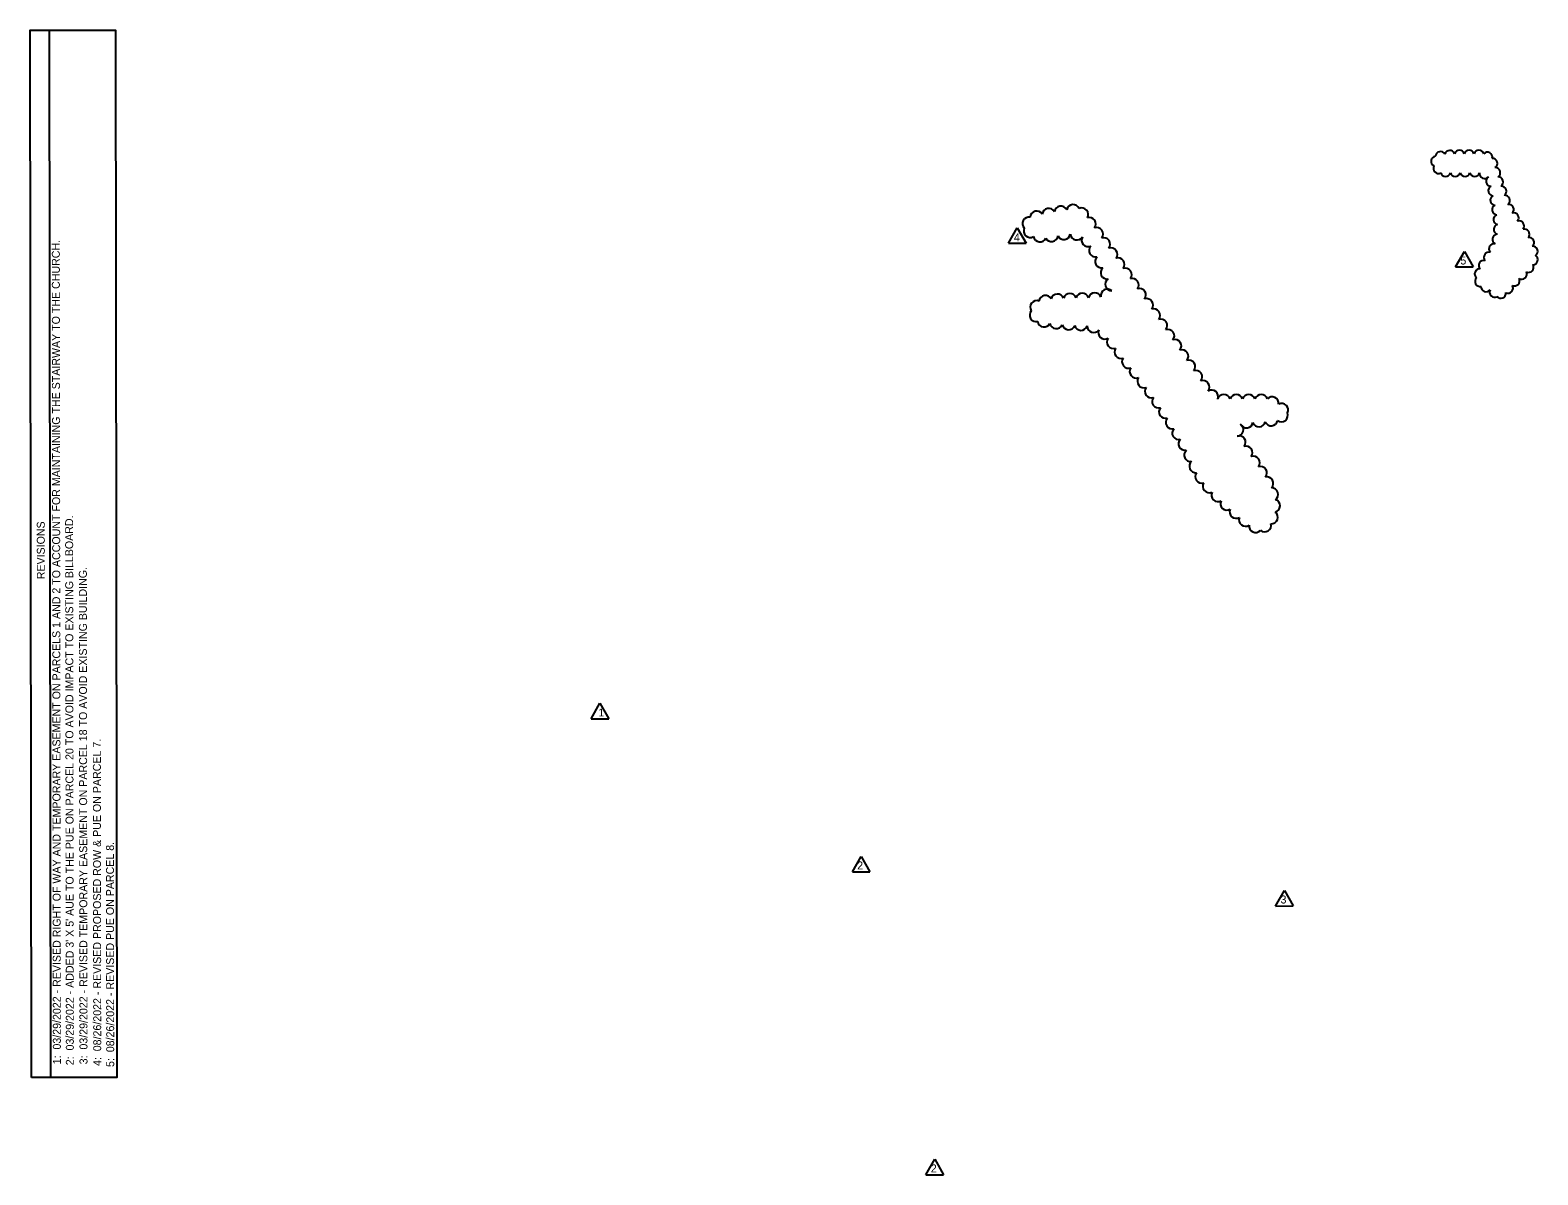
# Model space of a CAD drawing. Extents: x 1882804 to 2194450, y 87424 to 845437.
# Drawn here: x 1882804 to 1883942, y 844572 to 845437 of the extents above; entities that cross this region are included whole.
import ezdxf

# ---------------------------------------------------------------- set-up
doc = ezdxf.new("R2010")
doc.units = 0
doc.layers.add('Sheet Block Revision CELL', color=7, linetype='Continuous')

msp = doc.modelspace()

# ---------------------------------------------------------------- linework, layer by layer
at = {"layer": 'Sheet Block Revision CELL'}
for p, q in [((1882819.7, 844645.9), (1882818.7, 845436.6)), ((1883542.8, 845275.7), (1883549.4, 845287.4)), ((1883549.4, 845287.4), (1883556.1, 845275.7)), ((1883542.8, 845275.7), (1883556.1, 845275.7)), ((1883880.4, 845257.9), (1883887, 845269.6)), ((1883887, 845269.6), (1883893.7, 845257.9)), ((1883880.4, 845257.9), (1883893.7, 845257.9)), ((1883227.8, 844916.7), (1883234.3, 844928.5)), ((1883234.3, 844928.5), (1883241, 844916.8)), ((1883227.8, 844916.7), (1883241, 844916.8)), ((1883425, 844801.2), (1883431.5, 844812.9)), ((1883431.5, 844812.9), (1883438.2, 844801.2)), ((1883425, 844801.2), (1883438.2, 844801.2)), ((1883744.5, 844775.4), (1883751.1, 844787.2)), ((1883751.1, 844787.2), (1883757.8, 844775.5)), ((1883744.5, 844775.4), (1883757.8, 844775.5)), ((1883480.5, 844572.5), (1883487.1, 844584.2)), ((1883487.1, 844584.2), (1883493.7, 844572.5)), ((1883480.5, 844572.5), (1883493.7, 844572.5))]:
    msp.add_line(p, q, dxfattribs=at)
msp.add_lwpolyline([(1882805.2, 844645.9), (1882804.1, 845436.5), (1882868.6, 845436.6), (1882869.6, 844646)], close=True, dxfattribs=at)
for centre, radius, start, end in [((1883865.7, 845337.6), 3.85, 98.5677, 243.5677), ((1883869, 845341.1), 3.85, 30.5512, 175.5512), ((1883876, 845342), 3.85, 19.754, 164.754), ((1883883.3, 845342.2), 3.85, 17.5071, 162.5071), ((1883890.6, 845342.2), 3.85, 17.5, 162.5), ((1883898, 845342.2), 3.85, 17.5, 162.5), ((1883904.3, 845340.6), 3.85, 349.3585, 134.3585), ((1883867.4, 845332.3), 3.85, 152.0987, 297.0987), ((1883908.1, 845336), 3.85, 305.035, 90.035), ((1883910.3, 845329), 3.85, 305.035, 90.035), ((1883872.8, 845330.1), 3.85, 197.3072, 342.3072), ((1883880.1, 845330), 3.85, 197.5, 342.5), ((1883887.5, 845330), 3.85, 197.5, 342.5), ((1883894.8, 845330), 3.85, 197.5, 342.5), ((1883902.3, 845328.5), 3.85, 173.5372, 318.5372), ((1883907.2, 845322.6), 3.85, 121.3221, 266.3221), ((1883908.9, 845315.4), 3.85, 119.8498, 264.8498), ((1883912.5, 845322), 3.85, 305.3012, 90.3012), ((1883914.9, 845315), 3.85, 306.8133, 91.8133), ((1883910.4, 845308.3), 3.85, 119.3697, 264.3697), ((1883917.5, 845308.1), 3.85, 309.2572, 94.2572), ((1883558.3, 845290.5), 4.92, 78.9337, 223.9337), ((1883564.1, 845295.1), 4.92, 32.4745, 177.4745), ((1883573.2, 845297.2), 4.92, 28.9006, 173.9006), ((1883582.3, 845298.8), 4.92, 25.4829, 170.4829), ((1883591.6, 845300), 4.92, 23.7892, 168.7892), ((1883598.1, 845297.5), 4.92, 329.7462, 114.7462), ((1883603.9, 845290.3), 4.92, 322.6712, 107.6712), ((1883911.8, 845301), 3.85, 117.6133, 262.6133), ((1883912.8, 845293.6), 3.85, 112.7454, 257.7454), ((1883920.5, 845301.3), 3.85, 313.6939, 98.6939), ((1883924.2, 845294.9), 3.85, 321.2908, 106.2908), ((1883559.2, 845285), 4.92, 155.173, 300.173), ((1883609.3, 845282.7), 4.92, 322.6712, 107.6712), ((1883913, 845286.2), 3.85, 105.6199, 250.6199), ((1883928.3, 845288.8), 3.85, 321.0615, 106.0615), ((1883932.3, 845282.6), 3.85, 319.3192, 104.3192), ((1883566.5, 845281.7), 4.92, 190.6405, 335.6405), ((1883575.3, 845281.9), 4.92, 207.3475, 352.3475), ((1883584.6, 845283.4), 4.92, 206.1246, 351.1246), ((1883594.4, 845283.1), 4.92, 184.7569, 329.7569), ((1883602.9, 845278.1), 4.92, 149.6769, 294.6769), ((1883608.5, 845270.3), 4.92, 137.3078, 282.3078), ((1883614.7, 845275), 4.92, 322.6712, 107.6712), ((1883909.4, 845271.6), 3.85, 78.7837, 223.7837), ((1883912.1, 845278.7), 3.85, 94.608, 239.608), ((1883935.8, 845276.3), 3.85, 314.1507, 99.1507), ((1883938.5, 845269.7), 3.85, 304.9848, 89.9848), ((1883613.1, 845262.1), 4.92, 135.2656, 280.2656), ((1883620.1, 845267.3), 4.92, 322.6712, 107.6712), ((1883625.5, 845259.7), 4.92, 322.6712, 107.6712), ((1883901.7, 845259), 3.85, 76.612, 221.612), ((1883905.6, 845265.2), 3.85, 74.9742, 219.9742), ((1883938.6, 845263.3), 3.85, 273.0145, 58.0145), ((1883617.3, 845253.6), 4.92, 132.867, 277.867), ((1883630.9, 845252), 4.92, 322.6599, 107.6599), ((1883898.6, 845252.6), 3.85, 85.5429, 230.5429), ((1883898.9, 845247), 3.85, 135.584, 280.584), ((1883930.3, 845252.5), 3.85, 239.3787, 24.3787), ((1883935.5, 845257.6), 3.85, 244.1441, 29.1441), ((1883608, 845233.4), 4.92, 21.0229, 166.0229), ((1883617.4, 845236.2), 4.92, 47.0123, 192.0123), ((1883620.8, 845244.7), 4.92, 124.3827, 269.3827), ((1883636.3, 845244.3), 4.92, 322.602, 107.602), ((1883641.7, 845236.6), 4.92, 322.5309, 107.5309), ((1883903.4, 845243), 3.85, 176.7583, 321.7583), ((1883909.9, 845238.8), 3.85, 152.7321, 297.7321), ((1883914.5, 845238), 3.85, 221.6581, 6.6581), ((1883919.9, 845241.9), 3.85, 246.2799, 31.2799), ((1883924.9, 845247.4), 3.85, 243.1795, 28.1795), ((1883564.1, 845227.5), 4.92, 69.0266, 214.0266), ((1883570.7, 845231.4), 4.92, 27.349, 172.349), ((1883579.8, 845232.5), 4.92, 21.2186, 166.2186), ((1883589.2, 845232.9), 4.92, 18.9869, 163.9869), ((1883598.5, 845233.1), 4.92, 17.8673, 162.8673), ((1883647.1, 845229), 4.92, 322.4483, 107.4483), ((1883563.7, 845221.5), 4.92, 138.7154, 283.7154), ((1883569.7, 845217.4), 4.92, 188.7185, 333.7185), ((1883652.4, 845221.3), 4.92, 322.3506, 107.3506), ((1883657.8, 845213.6), 4.92, 322.2326, 107.2326), ((1883578.9, 845216.2), 4.92, 191.1828, 336.1828), ((1883588.2, 845215.4), 4.92, 193.5197, 338.5197), ((1883597.5, 845214.9), 4.92, 195.9911, 340.9911), ((1883607.1, 845213.2), 4.92, 178.7047, 323.7047), ((1883615.5, 845208.3), 4.92, 155.5881, 300.5881), ((1883663.1, 845205.8), 4.92, 322.0861, 107.0861), ((1883622, 845201.2), 4.92, 144.3767, 289.3767), ((1883627.7, 845193.7), 4.92, 144.6907, 289.6907), ((1883668.4, 845198.1), 4.92, 321.8974, 106.8974), ((1883673.7, 845190.4), 4.92, 321.6411, 106.6411), ((1883633.4, 845186.3), 4.92, 145.4515, 290.4515), ((1883639.2, 845178.9), 4.92, 146.0539, 291.0539), ((1883678.9, 845182.6), 4.92, 321.313, 106.313), ((1883645, 845171.5), 4.92, 145.1794, 290.1794), ((1883684.2, 845174.8), 4.92, 321.7744, 106.7744), ((1883689.6, 845167.1), 4.92, 323.2108, 108.2108), ((1883650.6, 845164), 4.92, 143.4482, 288.4482), ((1883656.1, 845156.3), 4.92, 141.9785, 286.9785), ((1883696.2, 845160), 4.92, 337.7701, 122.7701), ((1883705.4, 845156.7), 4.92, 17.5, 162.5), ((1883714.8, 845156.7), 4.92, 17.5, 162.5), ((1883724.2, 845156.7), 4.92, 17.5, 162.5), ((1883733.6, 845156.7), 4.92, 17.3847, 162.3847), ((1883741.9, 845154.9), 4.91, 352.9909, 137.9909), ((1883661.3, 845148.5), 4.92, 140.7128, 285.7128), ((1883748.8, 845145.9), 4.91, 235.666, 20.666), ((1883749.1, 845149.9), 4.92, 332.374, 117.374), ((1883666.4, 845140.5), 4.92, 139.6034, 284.6034), ((1883715.3, 845135), 4.92, 271.2638, 56.2638), ((1883722.5, 845141.2), 4.92, 205.5063, 350.5063), ((1883731.9, 845142.1), 4.92, 200.771, 345.771), ((1883741.2, 845142.8), 4.92, 202.9408, 347.9408), ((1883671.3, 845132.5), 4.92, 138.3836, 283.3836), ((1883676, 845124.4), 4.92, 136.5297, 281.5297), ((1883716.9, 845125.4), 4.92, 321.8378, 106.8378), ((1883680.4, 845115.9), 4.92, 133.1082, 278.1082), ((1883722.2, 845117.7), 4.92, 323.0093, 108.0093), ((1883727.7, 845110), 4.92, 323.1598, 108.1598), ((1883684.3, 845107.4), 4.92, 131.0339, 276.0339), ((1883688.7, 845099.5), 4.92, 142.4179, 287.4179), ((1883733, 845102.3), 4.92, 320.9693, 105.9693), ((1883694.4, 845092.3), 4.92, 149.6301, 294.6301), ((1883737.8, 845094.4), 4.92, 316.6657, 101.6657), ((1883741.5, 845086.1), 4.92, 306.4153, 91.4153), ((1883700.9, 845085.6), 4.92, 153.5895, 298.5895), ((1883707.7, 845079.2), 4.92, 154.7462, 299.7462), ((1883742.9, 845077.5), 4.92, 286.4049, 71.4049), ((1883714.6, 845073), 4.92, 156.1637, 301.1637), ((1883721.7, 845067), 4.92, 159.0683, 304.0683), ((1883741.2, 845068.9), 4.92, 267.0986, 52.0986), ((1883729.4, 845062.3), 4.92, 173.0057, 318.0057), ((1883736.2, 845062.8), 4.92, 229.5492, 14.5492)]:
    msp.add_arc(centre, radius, start, end, dxfattribs=at)

# ---------------------------------------------------------------- texts
for s, rotation, p in [('1:  03/29/2022 - REVISED RIGHT OF WAY AND TEMPORARY EASEMENT ON PARCELS 1 AND 2 TO ACCOUNT FOR MAINTAINING THE STAIRWAY TO THE CHURCH.', 90.0758, (1882827.3, 844655.9)), ('4', 0.2208, (1883546.9, 845277.2)), ('5', 0.2208, (1883884, 845259.7)), ("2:  03/29/2022 - ADDED 3' X 5' AUE TO THE PUE ON PARCEL 20 TO AVOID IMPACT TO EXISTING BILLBOARD.", 90.0758, (1882837.1, 844655.2)), ('REVISIONS', 90.0758, (1882815.2, 845022.1)), ('3:  03/29/2022 - REVISED TEMPORARY EASEMENT ON PARCEL 18 TO AVOID EXISTING BUILDING.', 90.0758, (1882847.4, 844655.9)), ('1', 0.2208, (1883233.2, 844918.5)), ('4:  08/26/2022 - REVISED PROPOSED ROW & PUE ON PARCEL 7.', 90.0758, (1882857.8, 844654.6)), ('5:  08/26/2022 - REVISED PUE ON PARCEL 8.', 90.0758, (1882867.6, 844653.9)), ('2', 0.2208, (1883428.6, 844803)), ('3', 0.2208, (1883748.2, 844777.3)), ('2', 0.2208, (1883484.2, 844574.3))]:
    msp.add_text(s, height=6, rotation=rotation, dxfattribs=at).set_placement(p)

doc.saveas('drawing.dxf')
